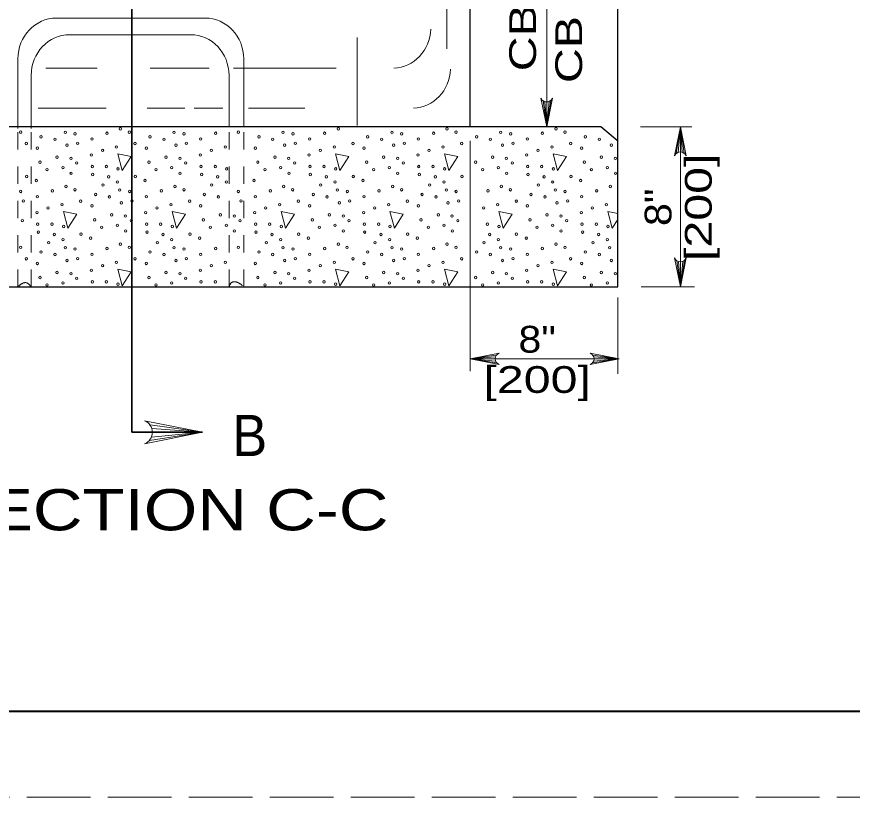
# Model space of a CAD drawing. Extents: x 1083.1 to 1117.1, y 697.4 to 719.4.
# Drawn here: x 1103.363 to 1108.233, y 697.354 to 701.901 of the extents above; entities that cross this region are included whole.
import ezdxf
from ezdxf.enums import TextEntityAlignment as Align

# ---------------------------------------------------------------- set-up
doc = ezdxf.new("R2010")
doc.units = 0
doc.header["$LTSCALE"] = 0.062
doc.linetypes.add('DOTTED', pattern=[1.5, 0.3, -1.2])
doc.linetypes.add('LONG_DASHED', pattern=[7.5, 6, -1.5])
doc.layers.add('1', color=7, linetype='Continuous', lineweight=13)

msp = doc.modelspace()

# ---------------------------------------------------------------- linework, layer by layer
at = {"layer": '1', "lineweight": 25}
for p, q in [((1106.86575, 701.19417), (1106.86575, 705.43083)), ((1106.00575, 701.25917), (1106.00575, 705.36217)), ((1106.76642, 701.25917), (1101.303, 701.25917)), ((1106.86175, 701.181), (1106.76642, 701.25917))]:
    msp.add_line(p, q, dxfattribs=at)
at = {"layer": '1'}
for p, q in [((1106.45208, 705.36217), (1106.45208, 701.25917)), ((1105.86958, 701.71342), (1105.86958, 702.35083)), ((1103.59475, 701.89342), (1104.462, 701.89342)), ((1103.67225, 701.79667), (1104.37642, 701.79667)), ((1105.34817, 701.7805), (1105.34817, 701.26842)), ((1103.3705, 701.25117), (1103.3705, 701.65592)), ((1104.68625, 701.26017), (1104.68625, 701.65592)), ((1103.53283, 701.60142), (1103.83183, 701.60142)), ((1104.14175, 701.60142), (1104.48517, 701.60142)), ((1104.62625, 701.60142), (1105.22583, 701.60142)), ((1103.44792, 701.25117), (1103.44792, 701.55925)), ((1104.60075, 701.26017), (1104.60075, 701.55925)), ((1106.43075, 701.41142), (1106.45208, 701.25917)), ((1106.44133, 701.40625), (1106.45208, 701.25917)), ((1106.47567, 701.41325), (1106.45208, 701.25917)), ((1106.46575, 701.40742), (1106.45208, 701.25917)), ((1106.45208, 701.40475), (1106.45208, 701.25917)), ((1103.48875, 701.368), (1103.88383, 701.368)), ((1104.12367, 701.368), (1104.34308, 701.368)), ((1104.39683, 701.368), (1104.56458, 701.368)), ((1104.71442, 701.368), (1105.04183, 701.368)), ((1106.99892, 701.25917), (1107.29817, 701.25917)), ((1107.20717, 701.10508), (1107.23075, 701.25917)), ((1107.21708, 701.11092), (1107.23075, 701.25917)), ((1107.23075, 701.11358), (1107.23075, 701.25917)), ((1107.2415, 701.112), (1107.23075, 701.25917)), ((1107.25208, 701.10683), (1107.23075, 701.25917)), ((1107.23075, 700.328), (1107.23075, 701.25917)), ((1106.00575, 701.17908), (1106.00575, 699.83558)), ((1106.80733, 700.76667), (1106.833, 700.66925)), ((1106.86567, 700.75525), (1106.80733, 700.76667)), ((1106.833, 700.66925), (1106.86567, 700.72083)), ((1107.20942, 700.48025), (1107.23075, 700.328)), ((1107.22, 700.47508), (1107.23075, 700.328)), ((1107.25433, 700.48208), (1107.23075, 700.328)), ((1107.24442, 700.47625), (1107.23075, 700.328)), ((1107.23075, 700.4735), (1107.23075, 700.328)), ((1107.00258, 700.328), (1107.305, 700.328)), ((1107.305, 700.328), (1107.31267, 700.328)), ((1106.86567, 700.26575), (1106.86567, 699.8205)), ((1106.86567, 700.26575), (1106.86567, 699.8205)), ((1106.86567, 700.26575), (1106.86567, 699.8205)), ((1106.86567, 700.26575), (1106.86567, 699.8205)), ((1106.86567, 700.20542), (1106.86567, 699.82483)), ((1106.15808, 699.92967), (1106.00575, 699.90833)), ((1106.15292, 699.91908), (1106.00575, 699.90833)), ((1106.00575, 699.90833), (1106.87333, 699.90833)), ((1106.15133, 699.90833), (1106.00575, 699.90833)), ((1106.15408, 699.89467), (1106.00575, 699.90833)), ((1106.15992, 699.88475), (1106.00575, 699.90833)), ((1106.71925, 699.88475), (1106.87333, 699.90833)), ((1106.72108, 699.92967), (1106.87333, 699.90833)), ((1106.72508, 699.89467), (1106.87333, 699.90833)), ((1106.72625, 699.91908), (1106.87333, 699.90833)), ((1106.72783, 699.90833), (1106.87333, 699.90833)), ((1104.14067, 699.52292), (1104.44533, 699.48033)), ((1104.151, 699.50183), (1104.44533, 699.48033)), ((1104.13708, 699.43317), (1104.44533, 699.48033)), ((1104.14875, 699.45292), (1104.44533, 699.48033)), ((1104.15417, 699.48033), (1104.44533, 699.48033))]:
    msp.add_line(p, q, dxfattribs=at)
at = {"layer": '1', "lineweight": 35}
for p, q in [((1104.03408, 699.48033), (1104.03408, 704.62275)), ((1104.44533, 699.48033), (1104.03408, 699.48033))]:
    msp.add_line(p, q, dxfattribs=at)
at = {"layer": '1', "linetype": 'DOTTED'}
for p, q in [((1104.60075, 700.328), (1104.60075, 701.26017)), ((1104.68625, 700.328), (1104.68625, 701.26017)), ((1103.3705, 700.328), (1103.3705, 701.25117)), ((1103.44792, 700.328), (1103.44792, 701.25117))]:
    msp.add_line(p, q, dxfattribs=at)
at = {"layer": '1', "linetype": 'LONG_DASHED'}
msp.add_lwpolyline([(1083.12642, 697.35408), (1117.12642, 697.35408), (1117.12642, 719.35408), (1083.12642, 719.35408)], close=True, dxfattribs=at)
at = {"layer": '1', "lineweight": 25}
for points in [[(1116.62642, 697.85408), (1085.12642, 697.85408), (1085.12642, 718.85408)], [(1101.2135, 701.176), (1101.2135, 700.328), (1106.86575, 700.328), (1106.86575, 701.19417)]]:
    msp.add_lwpolyline(points, dxfattribs=at)
at = {"layer": '1', "lineweight": 40}
msp.add_lwpolyline([(1085.12642, 718.85408), (1116.62642, 718.85408), (1116.62642, 697.85408), (1085.12642, 697.85408)], close=True, dxfattribs=at)
msp.add_lwpolyline([(1085.12642, 718.85408), (1116.62642, 718.85408), (1116.62642, 697.85408), (1085.12642, 697.85408)], close=True, dxfattribs=at)
at = {"layer": '1'}
for points in [[(1106.48575, 701.42733), (1106.45208, 701.25917), (1106.41842, 701.42733)], [(1107.19708, 701.09092), (1107.23075, 701.25917), (1107.26442, 701.09092)], [(1107.26442, 700.49617), (1107.23075, 700.328), (1107.19708, 700.49617)], [(1106.174, 699.87467), (1106.00575, 699.90833), (1106.174, 699.942)], [(1106.70517, 699.87467), (1106.87333, 699.90833), (1106.70517, 699.942)], [(1104.10883, 699.413), (1104.44533, 699.48033), (1104.10883, 699.54758)]]:
    msp.add_lwpolyline(points, dxfattribs=at)
for points in [[(1103.9525, 701.1025), (1103.97817, 701.00517), (1104.03033, 701.08733)], [(1105.22125, 701.1025), (1105.24692, 701.00517), (1105.29917, 701.08733)], [(1105.85575, 701.1025), (1105.88142, 701.00517), (1105.93358, 701.08733)], [(1106.49008, 701.1025), (1106.51575, 701.00517), (1106.568, 701.08733)], [(1103.63533, 700.76667), (1103.66092, 700.66925), (1103.71317, 700.75142)], [(1104.26967, 700.76667), (1104.29533, 700.66925), (1104.34758, 700.75142)], [(1104.90417, 700.76667), (1104.92975, 700.66925), (1104.982, 700.75142)], [(1105.5385, 700.76667), (1105.56417, 700.66925), (1105.61642, 700.75142)], [(1106.17292, 700.76667), (1106.1985, 700.66925), (1106.25083, 700.75142)], [(1103.9525, 700.43075), (1103.97817, 700.3335), (1104.03033, 700.41567)], [(1105.22125, 700.43075), (1105.24692, 700.3335), (1105.29917, 700.41567)], [(1105.85575, 700.43075), (1105.88142, 700.3335), (1105.93358, 700.41567)], [(1106.49008, 700.43075), (1106.51575, 700.3335), (1106.568, 700.41567)]]:
    msp.add_lwpolyline(points, close=True, dxfattribs=at)
for centre, radius, start, end in [((1106.45206, 701.44095), 0.03631, 202.08782, 337.91395), ((1107.23079, 701.07734), 0.03631, 22.08782, 157.91395), ((1107.23072, 700.50977), 0.03631, 202.08782, 337.91395), ((1106.1876, 699.90836), 0.03631, 112.08782, 247.91395), ((1106.69156, 699.90836), 0.03631, 292.08605, 67.91218), ((1104.08168, 699.48037), 0.07261, 292.08605, 67.91218)]:
    msp.add_arc(centre, radius, start, end, dxfattribs=at)
for centre, start_param, end_param in [((1103.59477, 701.65595), 6.2831853, 7.8539816), ((1104.46197, 701.65595), 4.712389, 6.2831853), ((1103.67222, 701.55922), 6.2831853, 7.8539816), ((1104.37643, 701.55922), 4.712389, 6.2831853), ((1105.55264, 701.83871), 3.178636, 4.6723832), ((1105.66725, 701.60529), 3.178636, 4.6723832)]:
    msp.add_ellipse(centre, major_axis=(0, 0.23746), ratio=0.944544, start_param=start_param, end_param=end_param, dxfattribs=at)
for centre in [(1103.96799, 701.24809), (1105.2368, 701.24809), (1105.8712, 701.24809), (1106.5056, 701.24809), (1103.38583, 701.22906), (1103.50573, 701.20186), (1103.64651, 701.22755), (1103.70387, 701.21933), (1103.88917, 701.22274), (1104.02023, 701.22906), (1104.14013, 701.20186), (1104.28091, 701.22755), (1104.33827, 701.21933), (1104.52357, 701.22274), (1104.65463, 701.22906), (1104.77453, 701.20186), (1104.91532, 701.22755), (1104.97268, 701.21933), (1105.15797, 701.22274), (1105.40893, 701.20186), (1105.54972, 701.22755), (1105.60708, 701.21933), (1105.79238, 701.22274), (1105.92343, 701.22906), (1106.04334, 701.20186), (1106.18412, 701.22755), (1106.24148, 701.21933), (1106.42678, 701.22274), (1106.55784, 701.22906), (1106.67774, 701.20186), (1103.41918, 701.16285), (1103.58651, 701.18765), (1103.65671, 701.15317), (1103.71841, 701.16408), (1103.80152, 701.18849), (1104.05359, 701.16285), (1104.22091, 701.18765), (1104.29112, 701.15317), (1104.35281, 701.16408), (1104.43592, 701.18849), (1104.85531, 701.18765), (1104.92552, 701.15317), (1104.98721, 701.16408), (1105.07032, 701.18849), (1105.32239, 701.16285), (1105.48971, 701.18765), (1105.55992, 701.15317), (1105.62162, 701.16408), (1105.70472, 701.18849), (1105.95679, 701.16285), (1106.12412, 701.18765), (1106.19432, 701.15317), (1106.25602, 701.16408), (1106.33913, 701.18849), (1106.59119, 701.16285), (1106.75852, 701.18765), (1106.82873, 701.15317), (1103.48432, 701.13565), (1103.86342, 701.12294), (1103.94484, 701.14197), (1104.11872, 701.13565), (1104.49783, 701.12294), (1104.57924, 701.14197), (1104.75312, 701.13565), (1105.13223, 701.12294), (1105.21364, 701.14197), (1105.38752, 701.13565), (1105.76663, 701.12294), (1105.84805, 701.14197), (1106.40103, 701.12294), (1106.48245, 701.14197), (1106.65633, 701.13565), (1103.49975, 701.05404), (1103.59909, 701.08309), (1103.67992, 701.0761), (1103.7984, 701.09574), (1104.13416, 701.05404), (1104.23349, 701.08309), (1104.31433, 701.0761), (1104.4328, 701.09574), (1104.76856, 701.05404), (1104.86789, 701.08309), (1104.94873, 701.0761), (1105.0672, 701.09574), (1105.40296, 701.05404), (1105.5023, 701.08309), (1105.58313, 701.0761), (1105.7016, 701.09574), (1106.03736, 701.05404), (1106.1367, 701.08309), (1106.21753, 701.0761), (1106.33601, 701.09574), (1106.67176, 701.05404), (1106.7711, 701.08309), (1106.85193, 701.0761), (1103.54088, 701.0105), (1103.6325, 701.02231), (1103.7136, 701.04951), (1103.80353, 701.02863), (1103.88579, 701.02863), (1103.9534, 701.01503), (1104.17529, 701.0105), (1104.2669, 701.02231), (1104.348, 701.04951), (1104.43793, 701.02863), (1104.52019, 701.02863), (1104.58781, 701.01503), (1104.80969, 701.0105), (1104.90131, 701.02231), (1104.9824, 701.04951), (1105.07233, 701.02863), (1105.15459, 701.02863), (1105.22221, 701.01503), (1105.44409, 701.0105), (1105.53571, 701.02231), (1105.61681, 701.04951), (1105.70673, 701.02863), (1105.78899, 701.02863), (1105.85661, 701.01503), (1106.07849, 701.0105), (1106.17011, 701.02231), (1106.25121, 701.04951), (1106.34113, 701.02863), (1106.4234, 701.02863), (1106.49101, 701.01503), (1106.71289, 701.0105), (1106.80451, 701.02231), (1103.42093, 700.97059), (1103.68077, 700.98934), (1103.80606, 700.9824), (1103.89948, 700.9688), (1104.05533, 700.97059), (1104.31517, 700.98934), (1104.44047, 700.9824), (1104.53388, 700.9688), (1104.94957, 700.98934), (1105.07487, 700.9824), (1105.16828, 700.9688), (1105.32414, 700.97059), (1105.58398, 700.98934), (1105.70927, 700.9824), (1105.80269, 700.9688), (1105.95854, 700.97059), (1106.21838, 700.98934), (1106.34367, 700.9824), (1106.43709, 700.9688), (1106.59294, 700.97059), (1106.85278, 700.98934), (1103.47744, 700.94703), (1103.65079, 700.91227), (1103.86601, 700.92072), (1103.94997, 700.93886), (1104.11185, 700.94703), (1104.2852, 700.91227), (1104.50042, 700.92072), (1104.58437, 700.93886), (1104.74625, 700.94703), (1104.9196, 700.91227), (1105.13482, 700.92072), (1105.21877, 700.93886), (1105.38065, 700.94703), (1105.554, 700.91227), (1105.76922, 700.92072), (1105.85317, 700.93886), (1106.1884, 700.91227), (1106.40362, 700.92072), (1106.48758, 700.93886), (1106.64945, 700.94703), (1106.8228, 700.91227), (1103.38667, 700.8835), (1103.57197, 700.88692), (1103.70303, 700.89324), (1103.82293, 700.86604), (1103.96371, 700.89173), (1104.02107, 700.8835), (1104.20637, 700.88692), (1104.33743, 700.89324), (1104.45733, 700.86604), (1104.65548, 700.8835), (1104.84077, 700.88692), (1104.97183, 700.89324), (1105.09173, 700.86604), (1105.23252, 700.89173), (1105.28988, 700.8835), (1105.47518, 700.88692), (1105.60623, 700.89324), (1105.72613, 700.86604), (1105.86692, 700.89173), (1105.92428, 700.8835), (1106.10958, 700.88692), (1106.24063, 700.89324), (1106.36054, 700.86604), (1106.50132, 700.89173), (1106.55868, 700.8835), (1106.74398, 700.88692), (1103.40121, 700.82826), (1103.48432, 700.85266), (1103.73639, 700.82703), (1103.90371, 700.85182), (1103.97392, 700.81734), (1104.03561, 700.82826), (1104.11872, 700.85266), (1104.37079, 700.82703), (1104.53811, 700.85182), (1104.67001, 700.82826), (1104.75312, 700.85266), (1105.00519, 700.82703), (1105.17251, 700.85182), (1105.24272, 700.81734), (1105.30442, 700.82826), (1105.38752, 700.85266), (1105.63959, 700.82703), (1105.80692, 700.85182), (1105.87712, 700.81734), (1105.93882, 700.82826), (1106.27399, 700.82703), (1106.44132, 700.85182), (1106.51152, 700.81734), (1106.57322, 700.82826), (1106.65633, 700.85266), (1103.4812, 700.75992), (1103.54622, 700.78712), (1103.62764, 700.80615), (1103.80152, 700.79982), (1104.1156, 700.75992), (1104.18063, 700.78712), (1104.26204, 700.80615), (1104.43592, 700.79982), (1104.75, 700.75992), (1104.81503, 700.78712), (1104.89644, 700.80615), (1105.07032, 700.79982), (1105.3844, 700.75992), (1105.44943, 700.78712), (1105.53084, 700.80615), (1105.70472, 700.79982), (1106.08383, 700.78712), (1106.16525, 700.80615), (1106.33913, 700.79982), (1106.65321, 700.75992), (1106.71823, 700.78712), (1106.79965, 700.80615), (1103.3964, 700.71369), (1103.81695, 700.71822), (1103.91629, 700.74727), (1103.99712, 700.74027), (1104.0308, 700.71369), (1104.45136, 700.71822), (1104.55069, 700.74727), (1104.63153, 700.74027), (1104.6652, 700.71369), (1105.08576, 700.71822), (1105.1851, 700.74727), (1105.26593, 700.74027), (1105.2996, 700.71369), (1105.72016, 700.71822), (1105.8195, 700.74727), (1105.90033, 700.74027), (1105.93401, 700.71369), (1106.35456, 700.71822), (1106.4539, 700.74727), (1106.53473, 700.74027), (1106.56841, 700.71369), (1103.48633, 700.69281), (1103.56859, 700.69281), (1103.6362, 700.67921), (1103.85808, 700.67467), (1103.9497, 700.68648), (1104.12073, 700.69281), (1104.20299, 700.69281), (1104.2706, 700.67921), (1104.49249, 700.67467), (1104.58411, 700.68648), (1104.75513, 700.69281), (1104.83739, 700.69281), (1104.90501, 700.67921), (1105.12689, 700.67467), (1105.21851, 700.68648), (1105.38953, 700.69281), (1105.47179, 700.69281), (1105.53941, 700.67921), (1105.76129, 700.67467), (1105.85291, 700.68648), (1106.10619, 700.69281), (1106.17381, 700.67921), (1106.39569, 700.67467), (1106.48731, 700.68648), (1106.65834, 700.69281), (1106.7406, 700.69281), (1106.80821, 700.67921), (1103.48886, 700.64658), (1103.58228, 700.63298), (1103.73813, 700.63477), (1103.99797, 700.65352), (1104.12326, 700.64658), (1104.21668, 700.63298), (1104.37253, 700.63477), (1104.63237, 700.65352), (1104.75767, 700.64658), (1104.85108, 700.63298), (1105.00693, 700.63477), (1105.26677, 700.65352), (1105.39207, 700.64658), (1105.48548, 700.63298), (1105.64134, 700.63477), (1105.90118, 700.65352), (1106.11989, 700.63298), (1106.27574, 700.63477), (1106.53558, 700.65352), (1106.66087, 700.64658), (1106.75429, 700.63298), (1103.54881, 700.5849), (1103.63277, 700.60303), (1103.79464, 700.6112), (1103.96799, 700.57645), (1104.18322, 700.5849), (1104.26717, 700.60303), (1104.42905, 700.6112), (1104.81762, 700.5849), (1104.90157, 700.60303), (1105.06345, 700.6112), (1105.2368, 700.57645), (1105.45202, 700.5849), (1105.53597, 700.60303), (1105.69785, 700.6112), (1105.8712, 700.57645), (1106.08642, 700.5849), (1106.17037, 700.60303), (1106.33225, 700.6112), (1106.5056, 700.57645), (1106.72082, 700.5849), (1106.80478, 700.60303), (1103.38583, 700.55742), (1103.50573, 700.53021), (1103.58651, 700.516), (1103.64651, 700.5559), (1103.70387, 700.54768), (1103.80152, 700.51684), (1103.88917, 700.55109), (1104.02023, 700.55742), (1104.14013, 700.53021), (1104.22091, 700.516), (1104.28091, 700.5559), (1104.33827, 700.54768), (1104.43592, 700.51684), (1104.52357, 700.55109), (1104.65463, 700.55742), (1104.77453, 700.53021), (1104.85531, 700.516), (1104.91532, 700.5559), (1104.97268, 700.54768), (1105.07032, 700.51684), (1105.15797, 700.55109), (1105.28903, 700.55742), (1105.40893, 700.53021), (1105.48971, 700.516), (1105.54972, 700.5559), (1105.60708, 700.54768), (1105.70472, 700.51684), (1105.79238, 700.55109), (1105.92343, 700.55742), (1106.04334, 700.53021), (1106.12412, 700.516), (1106.18412, 700.5559), (1106.24148, 700.54768), (1106.33913, 700.51684), (1106.42678, 700.55109), (1106.55784, 700.55742), (1106.67774, 700.53021), (1106.75852, 700.516), (1106.81852, 700.5559), (1103.41918, 700.4912), (1103.65671, 700.48152), (1103.71841, 700.49243), (1103.94484, 700.47032), (1104.05359, 700.4912), (1104.29112, 700.48152), (1104.35281, 700.49243), (1104.57924, 700.47032), (1104.92552, 700.48152), (1104.98721, 700.49243), (1105.21364, 700.47032), (1105.32239, 700.4912), (1105.55992, 700.48152), (1105.62162, 700.49243), (1105.84805, 700.47032), (1105.95679, 700.4912), (1106.19432, 700.48152), (1106.25602, 700.49243), (1106.48245, 700.47032), (1106.59119, 700.4912), (1106.82873, 700.48152), (1103.48432, 700.464), (1103.7984, 700.42409), (1103.86342, 700.45129), (1104.11872, 700.464), (1104.4328, 700.42409), (1104.49783, 700.45129), (1104.75312, 700.464), (1105.0672, 700.42409), (1105.13223, 700.45129), (1105.38752, 700.464), (1105.7016, 700.42409), (1105.76663, 700.45129), (1106.33601, 700.42409), (1106.40103, 700.45129), (1106.65633, 700.464), (1103.49975, 700.38239), (1103.59909, 700.41144), (1103.67992, 700.40445), (1103.7136, 700.37786), (1104.13416, 700.38239), (1104.23349, 700.41144), (1104.31433, 700.40445), (1104.348, 700.37786), (1104.76856, 700.38239), (1104.86789, 700.41144), (1104.94873, 700.40445), (1104.9824, 700.37786), (1105.40296, 700.38239), (1105.5023, 700.41144), (1105.58313, 700.40445), (1105.61681, 700.37786), (1106.03736, 700.38239), (1106.1367, 700.41144), (1106.21753, 700.40445), (1106.25121, 700.37786), (1106.67176, 700.38239), (1106.7711, 700.41144), (1106.85193, 700.40445), (1103.54088, 700.33885), (1103.6325, 700.35066), (1103.80353, 700.35698), (1103.88579, 700.35698), (1103.9534, 700.34338), (1104.17529, 700.33885), (1104.2669, 700.35066), (1104.43793, 700.35698), (1104.52019, 700.35698), (1104.80969, 700.33885), (1104.90131, 700.35066), (1105.07233, 700.35698), (1105.15459, 700.35698), (1105.22221, 700.34338), (1105.44409, 700.33885), (1105.53571, 700.35066), (1105.70673, 700.35698), (1105.78899, 700.35698), (1105.85661, 700.34338), (1106.07849, 700.33885), (1106.17011, 700.35066), (1106.34113, 700.35698), (1106.4234, 700.35698), (1106.49101, 700.34338), (1106.71289, 700.33885), (1106.80451, 700.35066)]:
    msp.add_ellipse(centre, major_axis=(0, 0.00718), ratio=0.944544, dxfattribs=at)
at = {"layer": '1', "linetype": 'DOTTED'}
for points in [[(1103.3705, 700.328), (1103.39892, 700.349), (1103.41508, 700.35242), (1103.44792, 700.328)], [(1104.60075, 700.328), (1104.62033, 700.35592), (1104.65283, 700.35242), (1104.68625, 700.328)]]:
    msp.add_spline(points, degree=3, dxfattribs=at)

# ---------------------------------------------------------------- texts
at = {"layer": '1', "width": 1.35}
for s, p in [('CB No. 2-4 = 4\'-0" [1200]', (1106.65833, 701.51433)), ('CB No. 2-3 = 3\'-0" [900]', (1106.38967, 701.58333))]:
    msp.add_text(s, height=0.156, rotation=90, dxfattribs=at).set_placement(p)
at = {"layer": '1'}
for s, width, p in [('[200]', 1.35, (1107.41342, 700.79125)), ('8"', 1.15, (1107.17875, 700.79125))]:
    msp.add_text(s, height=0.156, rotation=90, dxfattribs=dict(at, width=width)).set_placement(p, align=Align.CENTER)
for s, width, p in [('8"', 1.15, (1106.39633, 699.9445)), ('[200]', 1.35, (1106.39633, 699.70983))]:
    msp.add_text(s, height=0.156, dxfattribs=dict(at, width=width)).set_placement(p, align=Align.CENTER)
for s, width, p in [('B', 0.95, (1104.61983, 699.342)), ('SECTION C-C', 1.25, (1102.92242, 698.90933))]:
    msp.add_text(s, height=0.24, dxfattribs=dict(at, width=width)).set_placement(p)

doc.saveas('drawing.dxf')
